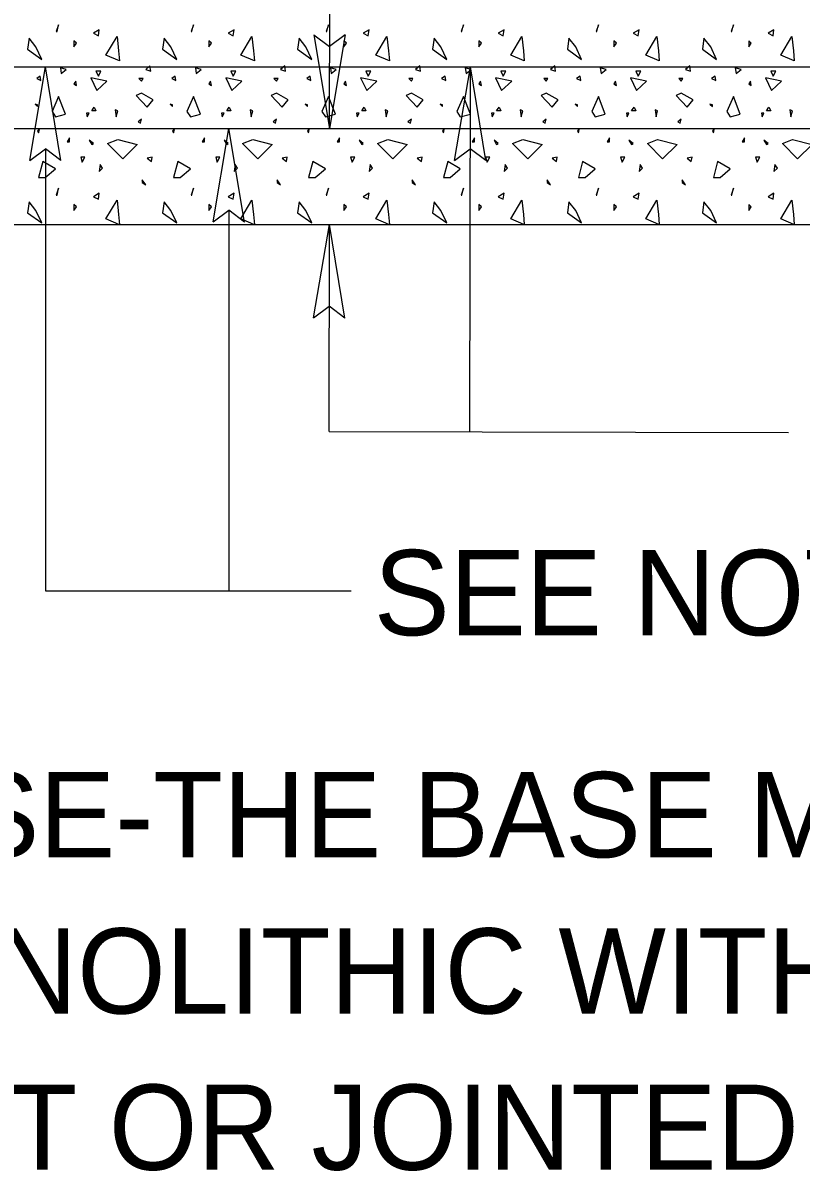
# Model space of a CAD drawing. Extents: x 9.6 to 16.8, y 2.2 to 12.2.
# Drawn here: x 12.138 to 12.686, y 6.208 to 7.016 of the extents above; entities that cross this region are included whole.
import ezdxf

# ---------------------------------------------------------------- set-up
doc = ezdxf.new("R2010")
doc.units = 0
for name, color, linetype in [('DETL-DIMS', 7, 'Continuous'), ('DETL-LINE', 7, 'Continuous'), ('DETL-NOTE', 7, 'Continuous'), ('DETL-PATT', 7, 'Continuous')]:
    doc.layers.add(name, color=color, linetype=linetype)

msp = doc.modelspace()

# ---------------------------------------------------------------- linework, layer by layer
at = {"layer": 'DETL-DIMS'}
for p, q in [((12.35376, 6.94224), (12.35408, 7.10043)), ((12.3429, 7.00816), (12.35376, 6.94224)), ((12.3429, 7.00816), (12.35388, 6.99988)), ((12.36486, 7.00808), (12.35376, 6.94224)), ((12.36486, 7.00808), (12.35388, 6.99988)), ((12.1428, 6.91965), (12.15389, 6.98549)), ((12.16476, 6.91957), (12.15389, 6.98549)), ((12.44189, 6.91965), (12.45299, 6.98549)), ((12.45251, 6.72859), (12.45299, 6.98549)), ((12.46385, 6.91957), (12.45299, 6.98549)), ((12.27194, 6.87639), (12.28304, 6.94224)), ((12.2939, 6.87631), (12.28304, 6.94224)), ((12.1428, 6.91965), (12.15378, 6.92785)), ((12.16476, 6.91957), (12.15378, 6.92785)), ((12.15378, 6.92785), (12.15378, 6.6167)), ((12.44189, 6.91965), (12.45287, 6.92784)), ((12.46385, 6.91957), (12.45287, 6.92784)), ((12.27194, 6.87639), (12.28292, 6.88459)), ((12.2939, 6.87631), (12.28292, 6.88459)), ((12.28292, 6.88459), (12.28292, 6.6167)), ((12.34267, 6.80882), (12.35376, 6.87467)), ((12.35349, 6.72878), (12.35376, 6.87467)), ((12.36463, 6.80875), (12.35376, 6.87467)), ((12.34267, 6.80882), (12.35365, 6.81702)), ((12.36463, 6.80875), (12.35365, 6.81702)), ((12.35349, 6.72878), (12.67698, 6.72816)), ((12.15378, 6.6167), (12.36902, 6.6167))]:
    msp.add_line(p, q, dxfattribs=at)
at = {"layer": 'DETL-LINE'}
for p, q in [((11.2322, 6.98549), (13.29365, 6.98549)), ((11.21522, 6.94224), (13.35086, 6.94224)), ((11.10965, 6.87467), (13.41718, 6.87467))]:
    msp.add_line(p, q, dxfattribs=at)
at = {"layer": 'DETL-PATT'}
for points in [[(12.16145, 7.01047), (12.162, 7.01047), (12.16314, 7.01525)], [(12.25647, 7.01047), (12.25702, 7.01047), (12.25816, 7.01525)], [(12.35149, 7.01047), (12.35204, 7.01047), (12.35318, 7.01525)], [(12.44647, 7.01047), (12.44706, 7.01047), (12.4482, 7.01525)], [(12.54149, 7.01047), (12.54208, 7.01047), (12.54318, 7.01525)], [(12.63651, 7.01047), (12.63706, 7.01047), (12.6382, 7.01525)], [(12.18757, 7.00933), (12.1911, 7.00749), (12.19165, 7.01173)], [(12.20537, 6.99678), (12.20592, 6.98973), (12.19647, 6.9938), (12.20424, 7.00694)], [(12.28259, 7.00933), (12.28612, 7.00749), (12.28667, 7.01173)], [(12.30035, 6.99678), (12.30094, 6.98973), (12.29149, 6.9938), (12.29925, 7.00694)], [(12.37761, 7.00933), (12.38114, 7.00749), (12.38169, 7.01173)], [(12.39537, 6.99678), (12.39596, 6.98973), (12.38647, 6.9938), (12.39424, 7.00694)], [(12.47259, 7.00933), (12.47612, 7.00749), (12.47671, 7.01173)], [(12.49039, 6.99678), (12.49094, 6.98973), (12.48149, 6.9938), (12.48925, 7.00694)], [(12.56761, 7.00933), (12.57114, 7.00749), (12.57173, 7.01173)], [(12.58541, 6.99678), (12.58596, 6.98973), (12.57651, 6.9938), (12.58427, 7.00694)], [(12.66263, 7.00933), (12.66616, 7.00749), (12.66671, 7.01173)], [(12.68043, 6.99678), (12.68098, 6.98973), (12.67153, 6.9938), (12.67929, 7.00694)], [(12.14239, 7.00565), (12.14125, 6.99804), (12.15129, 6.99082), (12.14718, 6.99973)], [(12.17388, 7.00396), (12.17388, 6.99973), (12.17573, 7.00212)], [(12.23741, 7.00565), (12.23627, 6.99804), (12.24631, 6.99082), (12.2422, 6.99973)], [(12.2689, 7.00396), (12.2689, 6.99973), (12.27071, 7.00212)], [(12.33243, 7.00565), (12.33129, 6.99804), (12.34129, 6.99082), (12.33722, 6.99973)], [(12.36388, 7.00396), (12.36388, 6.99973), (12.36573, 7.00212)], [(12.42741, 7.00565), (12.42631, 6.99804), (12.43631, 6.99082), (12.43224, 6.99973)], [(12.4589, 7.00396), (12.4589, 6.99973), (12.46075, 7.00212)], [(12.52243, 7.00565), (12.52129, 6.99804), (12.53133, 6.99082), (12.52725, 6.99973)], [(12.55392, 7.00396), (12.55392, 6.99973), (12.55576, 7.00212)], [(12.61745, 7.00565), (12.61631, 6.99804), (12.62635, 6.99082), (12.62224, 6.99973)], [(12.64894, 7.00396), (12.64894, 6.99973), (12.65078, 7.00212)], [(12.16443, 6.9849), (12.16498, 6.98082), (12.16851, 6.98376)], [(12.18941, 6.98251), (12.1911, 6.97898), (12.19294, 6.98251)], [(12.22737, 6.9862), (12.22443, 6.98376), (12.22796, 6.98251)], [(12.25941, 6.9849), (12.26, 6.98082), (12.26353, 6.98376)], [(12.28443, 6.98251), (12.28612, 6.97898), (12.28796, 6.98251)], [(12.32239, 6.9862), (12.31941, 6.98376), (12.32294, 6.98251)], [(12.35443, 6.9849), (12.35502, 6.98082), (12.35855, 6.98376)], [(12.37941, 6.98251), (12.38114, 6.97898), (12.38294, 6.98251)], [(12.41741, 6.9862), (12.41443, 6.98376), (12.41796, 6.98251)], [(12.44945, 6.9849), (12.45, 6.98082), (12.45353, 6.98376)], [(12.47443, 6.98251), (12.47612, 6.97898), (12.47796, 6.98251)], [(12.51243, 6.9862), (12.50945, 6.98376), (12.51298, 6.98251)], [(12.54447, 6.9849), (12.54502, 6.98082), (12.54855, 6.98376)], [(12.56945, 6.98251), (12.57114, 6.97898), (12.57298, 6.98251)], [(12.60741, 6.9862), (12.60447, 6.98376), (12.608, 6.98251)], [(12.63949, 6.9849), (12.64004, 6.98082), (12.64357, 6.98376)], [(12.66447, 6.98251), (12.66616, 6.97898), (12.668, 6.98251)], [(12.14776, 6.97729), (12.15071, 6.976), (12.15016, 6.97898)], [(12.17388, 6.97361), (12.17573, 6.97247), (12.17514, 6.97545)], [(12.18573, 6.97784), (12.18996, 6.96894), (12.19702, 6.97545)], [(12.21961, 6.97729), (12.22145, 6.97545), (12.22259, 6.97729)], [(12.24278, 6.97729), (12.24573, 6.976), (12.24518, 6.97898)], [(12.2689, 6.97361), (12.27071, 6.97247), (12.27016, 6.97545)], [(12.28075, 6.97784), (12.28498, 6.96894), (12.29204, 6.97545)], [(12.31463, 6.97729), (12.31647, 6.97545), (12.31761, 6.97729)], [(12.33776, 6.97729), (12.34075, 6.976), (12.3402, 6.97898)], [(12.36388, 6.97361), (12.36573, 6.97247), (12.36518, 6.97545)], [(12.37576, 6.97784), (12.38, 6.96894), (12.38706, 6.97545)], [(12.40965, 6.97729), (12.41149, 6.97545), (12.41259, 6.97729)], [(12.43278, 6.97729), (12.43576, 6.976), (12.43518, 6.97898)], [(12.4589, 6.97361), (12.46075, 6.97247), (12.4602, 6.97545)], [(12.47078, 6.97784), (12.47502, 6.96894), (12.48208, 6.97545)], [(12.50467, 6.97729), (12.50647, 6.97545), (12.50761, 6.97729)], [(12.5278, 6.97729), (12.53078, 6.976), (12.5302, 6.97898)], [(12.55392, 6.97361), (12.55576, 6.97247), (12.55518, 6.97545)], [(12.56576, 6.97784), (12.57, 6.96894), (12.57706, 6.97545)], [(12.59965, 6.97729), (12.60149, 6.97545), (12.60263, 6.97729)], [(12.62282, 6.97729), (12.62576, 6.976), (12.62522, 6.97898)], [(12.64894, 6.97361), (12.65078, 6.97247), (12.6502, 6.97545)], [(12.66078, 6.97784), (12.66502, 6.96894), (12.67208, 6.97545)], [(12.21776, 6.96541), (12.22553, 6.9571), (12.22976, 6.96231), (12.22145, 6.96714)], [(12.31278, 6.96541), (12.32055, 6.9571), (12.32478, 6.96231), (12.31647, 6.96714)], [(12.4078, 6.96541), (12.41557, 6.9571), (12.4198, 6.96231), (12.41149, 6.96714)], [(12.50282, 6.96541), (12.51059, 6.9571), (12.51482, 6.96231), (12.50647, 6.96714)], [(12.59784, 6.96541), (12.60561, 6.9571), (12.60984, 6.96231), (12.60149, 6.96714)], [(12.14831, 6.95878), (12.14663, 6.95937), (12.14831, 6.95765)], [(12.1609, 6.95047), (12.16796, 6.95231), (12.16314, 6.96471), (12.15847, 6.95412)], [(12.24333, 6.95878), (12.24165, 6.95937), (12.24333, 6.95765)], [(12.25588, 6.95047), (12.26294, 6.95231), (12.25816, 6.96471), (12.25349, 6.95412)], [(12.33835, 6.95878), (12.33667, 6.95937), (12.33835, 6.95765)], [(12.3509, 6.95047), (12.35796, 6.95231), (12.35318, 6.96471), (12.34851, 6.95412)], [(12.43337, 6.95878), (12.43165, 6.95937), (12.43337, 6.95765)], [(12.44592, 6.95047), (12.45298, 6.95231), (12.4482, 6.96471), (12.44353, 6.95412)], [(12.52835, 6.95878), (12.52667, 6.95937), (12.52835, 6.95765)], [(12.54094, 6.95047), (12.548, 6.95231), (12.54318, 6.96471), (12.53855, 6.95412)], [(12.62337, 6.95878), (12.62169, 6.95937), (12.62337, 6.95765)], [(12.63596, 6.95047), (12.64302, 6.95231), (12.6382, 6.96471), (12.63353, 6.95412)], [(12.18278, 6.95286), (12.18333, 6.95047), (12.18459, 6.95286)], [(12.18812, 6.9571), (12.18941, 6.95471), (12.18643, 6.95471)], [(12.20294, 6.95525), (12.20365, 6.95047), (12.20478, 6.95471)], [(12.27776, 6.95286), (12.27835, 6.95047), (12.27961, 6.95286)], [(12.28314, 6.9571), (12.28443, 6.95471), (12.28145, 6.95471)], [(12.29796, 6.95525), (12.29867, 6.95047), (12.2998, 6.95471)], [(12.37278, 6.95286), (12.37337, 6.95047), (12.37463, 6.95286)], [(12.37816, 6.9571), (12.37941, 6.95471), (12.37647, 6.95471)], [(12.39298, 6.95525), (12.39369, 6.95047), (12.39482, 6.95471)], [(12.4678, 6.95286), (12.46835, 6.95047), (12.46965, 6.95286)], [(12.47318, 6.9571), (12.47443, 6.95471), (12.47149, 6.95471)], [(12.488, 6.95525), (12.48871, 6.95047), (12.48984, 6.95471)], [(12.56282, 6.95286), (12.56337, 6.95047), (12.56467, 6.95286)], [(12.5682, 6.9571), (12.56945, 6.95471), (12.56647, 6.95471)], [(12.58302, 6.95525), (12.58373, 6.95047), (12.58482, 6.95471)], [(12.65784, 6.95286), (12.65839, 6.95047), (12.65965, 6.95286)], [(12.66318, 6.9571), (12.66447, 6.95471), (12.66149, 6.95471)], [(12.678, 6.95525), (12.67871, 6.95047), (12.67984, 6.95471)], [(12.21906, 6.94694), (12.22075, 6.9458), (12.22145, 6.94878)], [(12.31408, 6.94694), (12.31576, 6.9458), (12.31647, 6.94878)], [(12.40906, 6.94694), (12.41078, 6.9458), (12.41149, 6.94878)], [(12.50408, 6.94694), (12.50576, 6.9458), (12.50647, 6.94878)], [(12.5991, 6.94694), (12.60078, 6.9458), (12.60149, 6.94878)], [(12.14961, 6.94157), (12.14831, 6.94043), (12.14902, 6.93918)], [(12.1709, 6.93565), (12.16922, 6.93267), (12.1709, 6.93267)], [(12.18643, 6.93098), (12.18757, 6.93153), (12.18459, 6.93396)], [(12.20478, 6.93451), (12.21847, 6.93098), (12.20831, 6.92082), (12.19761, 6.93153)], [(12.24459, 6.94157), (12.24333, 6.94043), (12.24404, 6.93918)], [(12.26592, 6.93565), (12.26424, 6.93267), (12.26592, 6.93267)], [(12.28145, 6.93098), (12.28259, 6.93153), (12.27961, 6.93396)], [(12.2998, 6.93451), (12.31349, 6.93098), (12.30333, 6.92082), (12.29259, 6.93153)], [(12.33961, 6.94157), (12.33835, 6.94043), (12.33906, 6.93918)], [(12.36094, 6.93565), (12.35925, 6.93267), (12.36094, 6.93267)], [(12.37647, 6.93098), (12.37761, 6.93153), (12.37463, 6.93396)], [(12.39482, 6.93451), (12.40851, 6.93098), (12.39835, 6.92082), (12.38761, 6.93153)], [(12.43463, 6.94157), (12.43337, 6.94043), (12.43408, 6.93918)], [(12.45596, 6.93565), (12.45424, 6.93267), (12.45596, 6.93267)], [(12.47149, 6.93098), (12.47259, 6.93153), (12.46965, 6.93396)], [(12.48984, 6.93451), (12.50353, 6.93098), (12.49337, 6.92082), (12.48263, 6.93153)], [(12.52965, 6.94157), (12.52835, 6.94043), (12.52906, 6.93918)], [(12.55094, 6.93565), (12.54925, 6.93267), (12.55094, 6.93267)], [(12.56647, 6.93098), (12.56761, 6.93153), (12.56467, 6.93396)], [(12.58482, 6.93451), (12.59855, 6.93098), (12.58835, 6.92082), (12.57765, 6.93153)], [(12.62467, 6.94157), (12.62337, 6.94043), (12.62408, 6.93918)], [(12.64596, 6.93565), (12.64427, 6.93267), (12.64596, 6.93267)], [(12.66149, 6.93098), (12.66263, 6.93153), (12.65965, 6.93396)], [(12.67984, 6.93451), (12.69353, 6.93098), (12.68337, 6.92082), (12.67267, 6.93153)], [(12.15369, 6.90769), (12.1609, 6.91376), (12.152, 6.91898), (12.14902, 6.90769)], [(12.17867, 6.92196), (12.1798, 6.91843), (12.18165, 6.92196)], [(12.22553, 6.92137), (12.22851, 6.91898), (12.22906, 6.92196)], [(12.24871, 6.90769), (12.25588, 6.91376), (12.24702, 6.91898), (12.24404, 6.90769)], [(12.27369, 6.92196), (12.27482, 6.91843), (12.27667, 6.92196)], [(12.32055, 6.92137), (12.32353, 6.91898), (12.32408, 6.92196)], [(12.34373, 6.90769), (12.3509, 6.91376), (12.342, 6.91898), (12.33906, 6.90769)], [(12.36871, 6.92196), (12.36984, 6.91843), (12.37165, 6.92196)], [(12.41557, 6.92137), (12.41855, 6.91898), (12.4191, 6.92196)], [(12.43871, 6.90769), (12.44592, 6.91376), (12.43702, 6.91898), (12.43408, 6.90769)], [(12.46373, 6.92196), (12.46482, 6.91843), (12.46667, 6.92196)], [(12.51059, 6.92137), (12.51353, 6.91898), (12.51412, 6.92196)], [(12.53373, 6.90769), (12.54094, 6.91376), (12.53204, 6.91898), (12.52906, 6.90769)], [(12.55871, 6.92196), (12.55984, 6.91843), (12.56169, 6.92196)], [(12.60561, 6.92137), (12.60855, 6.91898), (12.60914, 6.92196)], [(12.62875, 6.90769), (12.63596, 6.91376), (12.62706, 6.91898), (12.62408, 6.90769)], [(12.65373, 6.92196), (12.65486, 6.91843), (12.65671, 6.92196)], [(12.19235, 6.91671), (12.19165, 6.91192), (12.19408, 6.91431)], [(12.28737, 6.91671), (12.28667, 6.91192), (12.28906, 6.91431)], [(12.38239, 6.91671), (12.38169, 6.91192), (12.38408, 6.91431)], [(12.47741, 6.91671), (12.47671, 6.91192), (12.4791, 6.91431)], [(12.57243, 6.91671), (12.57173, 6.91192), (12.57412, 6.91431)], [(12.66741, 6.91671), (12.66671, 6.91192), (12.66914, 6.91431)], [(12.222, 6.906), (12.222, 6.90416), (12.22443, 6.90247)], [(12.31702, 6.906), (12.31702, 6.90416), (12.31941, 6.90247)], [(12.41204, 6.906), (12.41204, 6.90416), (12.41443, 6.90247)], [(12.50706, 6.906), (12.50706, 6.90416), (12.50945, 6.90247)], [(12.60208, 6.906), (12.60208, 6.90416), (12.60447, 6.90247)], [(12.16145, 6.89525), (12.162, 6.89525), (12.16314, 6.90008)], [(12.18757, 6.89412), (12.1911, 6.89231), (12.19165, 6.89655)], [(12.25647, 6.89525), (12.25702, 6.89525), (12.25816, 6.90008)], [(12.28259, 6.89412), (12.28612, 6.89231), (12.28667, 6.89655)], [(12.35149, 6.89525), (12.35204, 6.89525), (12.35318, 6.90008)], [(12.37761, 6.89412), (12.38114, 6.89231), (12.38169, 6.89655)], [(12.44647, 6.89525), (12.44706, 6.89525), (12.4482, 6.90008)], [(12.47259, 6.89412), (12.47612, 6.89231), (12.47671, 6.89655)], [(12.54149, 6.89525), (12.54208, 6.89525), (12.54318, 6.90008)], [(12.56761, 6.89412), (12.57114, 6.89231), (12.57173, 6.89655)], [(12.63651, 6.89525), (12.63706, 6.89525), (12.6382, 6.90008)], [(12.66263, 6.89412), (12.66616, 6.89231), (12.66671, 6.89655)], [(12.14239, 6.89047), (12.14125, 6.88282), (12.15129, 6.87565), (12.14718, 6.88455)], [(12.17388, 6.88878), (12.17388, 6.88455), (12.17573, 6.88694)], [(12.23741, 6.89047), (12.23627, 6.88282), (12.24631, 6.87565), (12.2422, 6.88455)], [(12.2689, 6.88878), (12.2689, 6.88455), (12.27071, 6.88694)], [(12.33243, 6.89047), (12.33129, 6.88282), (12.34129, 6.87565), (12.33722, 6.88455)], [(12.36388, 6.88878), (12.36388, 6.88455), (12.36573, 6.88694)], [(12.42741, 6.89047), (12.42631, 6.88282), (12.43631, 6.87565), (12.43224, 6.88455)], [(12.4589, 6.88878), (12.4589, 6.88455), (12.46075, 6.88694)], [(12.52243, 6.89047), (12.52129, 6.88282), (12.53133, 6.87565), (12.52725, 6.88455)], [(12.55392, 6.88878), (12.55392, 6.88455), (12.55576, 6.88694)], [(12.61745, 6.89047), (12.61631, 6.88282), (12.62635, 6.87565), (12.62224, 6.88455)], [(12.64894, 6.88878), (12.64894, 6.88455), (12.65078, 6.88694)]]:
    msp.add_lwpolyline(points, close=True, dxfattribs=at)
for points in [[(12.20557, 6.87467), (12.19647, 6.87859), (12.20424, 6.89173), (12.20537, 6.88157), (12.20592, 6.87467)], [(12.30059, 6.87467), (12.29149, 6.87859), (12.29925, 6.89173), (12.30035, 6.88157), (12.30094, 6.87467)], [(12.39561, 6.87467), (12.38647, 6.87859), (12.39424, 6.89173), (12.39537, 6.88157), (12.39596, 6.87467)], [(12.49059, 6.87467), (12.48149, 6.87859), (12.48925, 6.89173), (12.49039, 6.88157), (12.49094, 6.87467)], [(12.58561, 6.87467), (12.57651, 6.87859), (12.58427, 6.89173), (12.58541, 6.88157), (12.58596, 6.87467)], [(12.68063, 6.87467), (12.67153, 6.87859), (12.67929, 6.89173), (12.68043, 6.88157), (12.68098, 6.87467)]]:
    msp.add_lwpolyline(points, dxfattribs=at)

# ---------------------------------------------------------------- texts
at = {"layer": 'DETL-NOTE'}
for s, p in [('SEE NOTE 2', (12.38497, 6.58547)), ('BASE-THE BASE MAY BE CAST', (11.98898, 6.42918)), ('MONOLITHIC WITH THE BASE', (11.98898, 6.31918)), ('UNIT OR JOINTED PER', (11.98898, 6.20918))]:
    msp.add_text(s, height=0.06, dxfattribs=at).set_placement(p)

doc.saveas('drawing.dxf')
